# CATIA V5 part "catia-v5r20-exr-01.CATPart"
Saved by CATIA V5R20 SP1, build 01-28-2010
Part number: Part1
Bounding box of the stored display mesh (mm): x -1 to 1, y -75.664 to 150, z -99.993 to 99.985
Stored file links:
  D:\v5_r20\psrt_files_downloaded\c03-catia-v5r20-prt\catia-v5r20-exr-01.CATPart
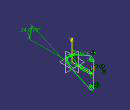
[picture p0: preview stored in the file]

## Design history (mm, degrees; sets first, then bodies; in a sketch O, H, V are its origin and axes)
Body1 (main body)
  Sketch1 on yz-plane, origin (0, 0, 0), H (0, 1, 0), V (0, 0, 1)
    arc A1 centre (0, 0) radius 40 from (-16.3197, 36.5194) to (-16.3197, -36.5194) ccw
    point P1 (40, 0)
    arc A2 centre (130, 80) radius 20 from (150, 80) to (121.8402, 98.2597) ccw
    arc A3 centre (130, -80) radius 20 from (150, -80) to (121.8402, -98.2597) cw
    line L1 (121.8402, 98.2597) -> (-16.3197, 36.5194)
    line L2 (150, 80) -> (150, -80)
    point P7 (150, -80)
    line L3 (121.8402, -98.2597) -> (-16.3197, -36.5194)
    point P8 (121.8402, -98.2597)
    point P10 (121.8402, -98.2597)
    point P11 (150, -80)
    circle A4 centre (0, 0) radius 30
    circle A5 centre (130, 80) radius 10
    circle A6 centre (130, -80) radius 10
    construction line L4 (60, 0) -> (120, 0)
    point P12 (60, 0)
    point P13 (120, 0)
    line L5 (60, 10) -> (120, 10)
    line L6 (120, -10) -> (60, -10)
    arc A7 centre (120, 0) radius 10 from (120, 10) to (120, -10) cw
    arc A8 centre (60, 0) radius 10 from (60, -10) to (60, 10) cw
    point P14 (60, 10)
    point P15 (120, 10)
    reference intersected line E2 through (0, 0) direction (-1, 0) from xy-plane
    reference intersected line E4 through (0, 0) direction (0, 1) from zx-plane
    radius A2 = 20
    radius A5 = 10
    radius A6 = 10
    radius A7 = 10
    radius A1 = 40
    radius A4 = 30
    distance V L2 = 150
    angle L3 L6 = 24.0787
    distance P14 P15 = 60
    distance P12 V = 60
    coincidence: A1 P1, P1 H, A3 P7, A3 P8, L2 P11, L3 P10, E2 P1, E2 L4, E2 P12, E2 P13, O L4, P7 P11, P8 P10
    symmetry: A2 A3 H
    tangency: L1 A2, L1 A1, L2 A2, L2 A3, L3 A3, L3 A1, A7 L5, A8 L5, A7 L6, A8 L6
    horizontal: L4 H, L6 H, L5 H, E2 H
    parallelism: L4 L5
    vertical: L2 V, E4 V
    perpendicularity: E2 L2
